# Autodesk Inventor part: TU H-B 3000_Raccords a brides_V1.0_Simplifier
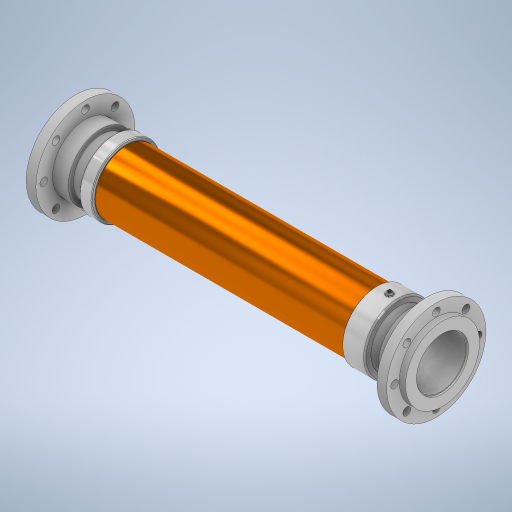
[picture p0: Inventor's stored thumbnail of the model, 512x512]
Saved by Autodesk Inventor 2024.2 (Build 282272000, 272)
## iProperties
Created: 2024-05
Part Number: TU H-B 3000_Raccords a brides_V1.0_Simplifier
Material: Générique
Document SubType Name: Modeling
Designer: Massimo Maselli
Density: 1 g/cm^3
Appearance: Par défaut
Author: Massimo Maselli
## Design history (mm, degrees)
derived "TU H-B 3000_Raccords a brides_V1.0.iam"
node "Solide1"
node "Solide2"
body "Srf1"
body "Srf2"
node "Solide3"
node "Solide4"
node "Solide5"
node "TU H Max_Sans raccord_V1.0.iam:1::VENT-PS1NBK-N8001.ipt:1"
node "Solide6"
node "TU H Max_Sans raccord_V1.0.iam:1::Nut.ipt:1"
node "Solide7"
node "TU H Max_Vortex_V1.0.ipt:1"
node "Solide8"
node "Collet 3.72.161.ipt:1"
node "Solide9"
node "Collet 3.72.161.ipt:2"
node "Solide10"
node "Flange 6''.ipt:1"
node "Solide11"
node "Flange 6''.ipt:2"
node "Solide12"
feature "Srf1::Dérivé"
feature "Srf1::Dérivé_1"
